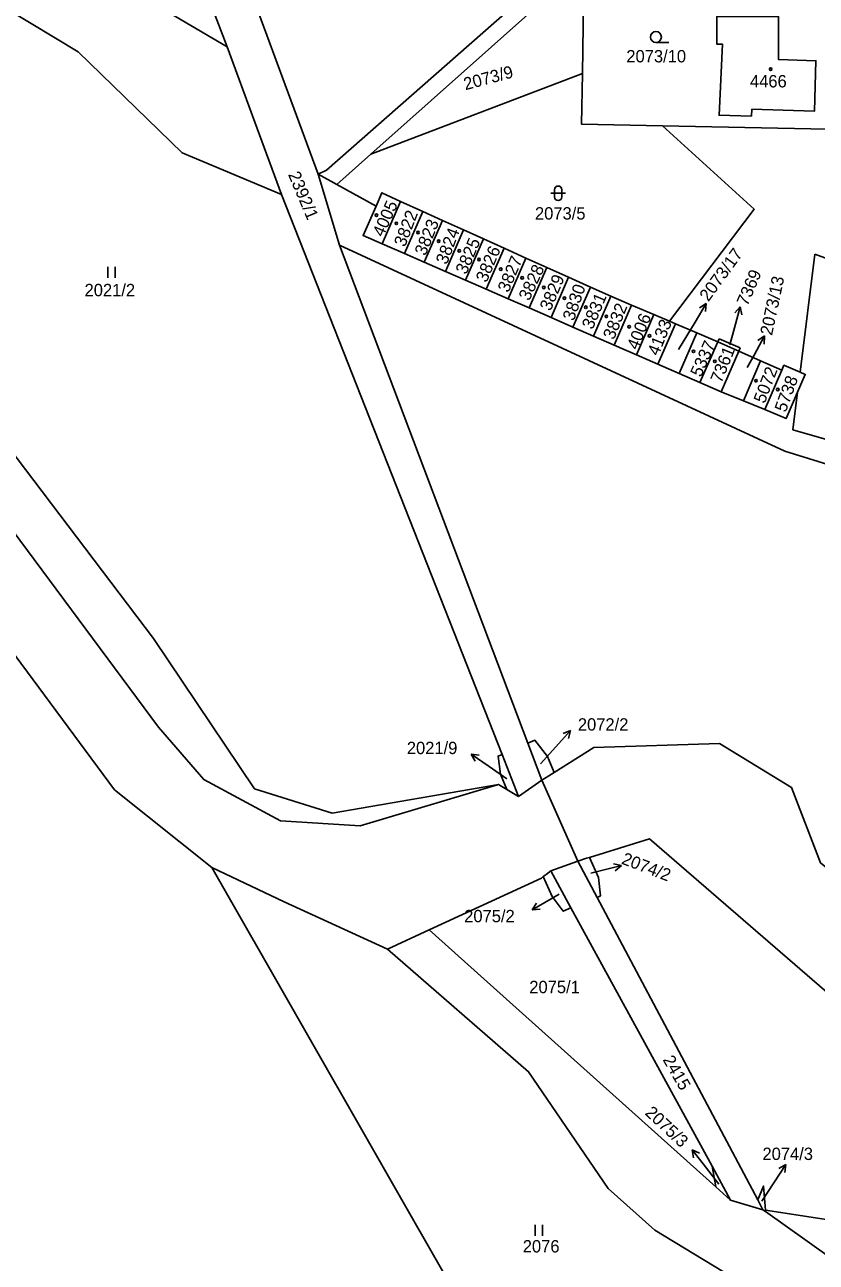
# Model space of a CAD drawing. Extents: x -667048 to -665920, y -1108425 to -1107247.
# Drawn here: x -666229.9 to -666121, y -1108187.1 to -1108016.8 of the extents above; entities that cross this region are included whole.
import ezdxf

# ---------------------------------------------------------------- set-up
doc = ezdxf.new("R2010")
doc.units = 0
for name, color, linetype in [('Default', 7, 'Continuous'), ('Hranice parcel', 7, 'Continuous'), ('Parcelní čísla', 7, 'Continuous'), ('Pop_ PČ_ popisy', 7, 'Continuous'), ('Značky budov', 7, 'Continuous'), ('Značky kultur', 7, 'Continuous')]:
    doc.layers.add(name, color=color, linetype=linetype)

# ---------------------------------------------------------------- blocks, each defined once
blk = doc.blocks.new('3.041')
at = {"layer": 'Default'}
blk.add_line((8, 0), (1758, 0), dxfattribs=at)
blk.add_circle((8, 750), 750, dxfattribs=at)
blk = doc.blocks.new('4.021')
at = {"layer": 'Default'}
blk.add_circle((-7, 1), 175, dxfattribs=at)
blk = doc.blocks.new('3.161')
at = {"layer": 'Default'}
for p, q in [((-1000, 1000), (1000, 1000)), ((-500, 1500), (-500, 500)), ((500, 500), (500, 1500))]:
    blk.add_line(p, q, dxfattribs=at)
for centre, start, end in [((0, 1500), 0, 180), ((0, 500), 180, 359.98789)]:
    blk.add_arc(centre, 500, start, end, dxfattribs=at)
blk = doc.blocks.new('10291')
at = {"layer": 'Default'}
for p, q in [((0, 3001), (-500, 2001)), ((0, 1), (0, 3001)), ((0, 3001), (500, 2001))]:
    blk.add_line(p, q, dxfattribs=at)
blk = doc.blocks.new('3.061')
at = {"layer": 'Default'}
for p, q in [((-511, -1), (-511, 1499)), ((489, -1), (489, 1499))]:
    blk.add_line(p, q, dxfattribs=at)

msp = doc.modelspace()

# ---------------------------------------------------------------- linework, layer by layer
at = {"layer": 'Hranice parcel'}
for points in [[(-666367.6, -1107733.37), (-666382.25, -1107746.6), (-666386.05, -1107757.21), (-666386.95, -1107822.21), (-666377, -1107854.78), (-666312.82, -1107976.82), (-666211.46, -1108113.47), (-666205.22, -1108120.66), (-666194.69, -1108126.35), (-666183.7, -1108127.05), (-666164.66, -1108121.36)], [(-666194.54, -1108040.18), (-666208.21, -1108034.43), (-666222.53, -1108020.57), (-666296.79, -1107975.73), (-666311.08, -1107963.6), (-666312.87, -1107961.82)], [(-666214.88, -1107968.55), (-666193.61, -1107981.03), (-666157.63, -1107981.49), (-666157.93, -1108008.07), (-666158.55, -1108010.61), (-666188.36, -1108036.81), (-666189.5, -1108037.4)], [(-666214.88, -1107968.55), (-666189.5, -1108037.4)], [(-666308.12, -1107969.91), (-666292.75, -1107996.41), (-666271.46, -1108022.33), (-666235.68, -1108070.26), (-666212.14, -1108101.26), (-666198.27, -1108121.92), (-666187.57, -1108125.3), (-666164.66, -1108121.36)], [(-666320.26, -1107983.17), (-666217.49, -1108122.07), (-666204.14, -1108132.75)], [(-666202.03, -1108019.86), (-666212.57, -1107992.25)], [(-666182.24, -1108034.63), (-666157.34, -1108012.43), (-666154.99, -1108010.84), (-666152.92, -1108010.37)], [(-666153.12, -1108023.51), (-666152.92, -1108010.37)], [(-666202.03, -1108019.86), (-666214.13, -1108012.7)], [(-666129.85, -1108029.41), (-666134.32, -1108029.28), (-666133.84, -1108019.5), (-666134.65, -1108019.49), (-666134.65, -1108015.69), (-666126.14, -1108015.7), (-666126.15, -1108021.62), (-666121, -1108021.77), (-666121.2, -1108028.69), (-666129.82, -1108028.44), (-666129.85, -1108029.41)], [(-666198.22, -1108030.21), (-666202.03, -1108019.86)], [(-666117.06, -1108022.14), (-666117.18, -1108031.25), (-666142.12, -1108030.72)], [(-666153.12, -1108023.51), (-666182.24, -1108034.63)], [(-666142.12, -1108030.72), (-666153.26, -1108030.49), (-666153.12, -1108023.51)], [(-666194.54, -1108040.18), (-666198.22, -1108030.21)], [(-666141.14, -1108057.61), (-666129.51, -1108042.2), (-666142.12, -1108030.72)], [(-666186.91, -1108038.79), (-666182.24, -1108034.63)], [(-666189.5, -1108037.4), (-666186.54, -1108047.13)], [(-666189.5, -1108037.4), (-666186.91, -1108038.79)], [(-666186.91, -1108038.79), (-666181.53, -1108041.76)], [(-666164.19, -1108117.23), (-666194.54, -1108040.18)], [(-666181.53, -1108041.76), (-666180.73, -1108039.94), (-666178.14, -1108041.12)], [(-666178.14, -1108041.12), (-666180.68, -1108046.96)], [(-666178.14, -1108041.12), (-666175.08, -1108042.51)], [(-666180.68, -1108046.96), (-666183.3, -1108045.82), (-666181.53, -1108041.76)], [(-666177.6, -1108048.3), (-666175.08, -1108042.51)], [(-666175.08, -1108042.51), (-666172.39, -1108043.73)], [(-666174.89, -1108049.48), (-666172.39, -1108043.73)], [(-666172.39, -1108043.73), (-666169.49, -1108045.04)], [(-666171.97, -1108050.75), (-666169.49, -1108045.04)], [(-666169.49, -1108045.04), (-666166.75, -1108046.28)], [(-666169.22, -1108051.95), (-666166.75, -1108046.28)], [(-666166.75, -1108046.28), (-666163.91, -1108047.56)], [(-666160.63, -1108115.67), (-666186.54, -1108047.13)], [(-666186.54, -1108047.13), (-666125.26, -1108075.48), (-666112.86, -1108079.33), (-666065.13, -1108092.87), (-666009.99, -1108116.41), (-665977.71, -1108122.7), (-665927.32, -1108129.44)], [(-666177.6, -1108048.3), (-666180.68, -1108046.96)], [(-666166.36, -1108053.2), (-666163.91, -1108047.56)], [(-666163.91, -1108047.56), (-666160.9, -1108048.92)], [(-666174.89, -1108049.48), (-666177.6, -1108048.3)], [(-666171.97, -1108050.75), (-666174.89, -1108049.48)], [(-666163.34, -1108054.52), (-666160.9, -1108048.92)], [(-666160.9, -1108048.92), (-666158.04, -1108050.21)], [(-666121.17, -1108048.37), (-666123.18, -1108064.62)], [(-666011.71, -1108072.54), (-666017.56, -1108086.38), (-666121.17, -1108048.37)], [(-666169.22, -1108051.95), (-666171.97, -1108050.75)], [(-666160.46, -1108055.78), (-666158.04, -1108050.21)], [(-666158.04, -1108050.21), (-666155.04, -1108051.57)], [(-666166.36, -1108053.2), (-666169.22, -1108051.95)], [(-666163.34, -1108054.52), (-666166.36, -1108053.2)], [(-666157.45, -1108057.1), (-666155.04, -1108051.57)], [(-666155.04, -1108051.57), (-666152.04, -1108052.93)], [(-666154.43, -1108058.42), (-666152.04, -1108052.93)], [(-666152.04, -1108052.93), (-666149.22, -1108054.17)], [(-666160.46, -1108055.78), (-666163.34, -1108054.52)], [(-666151.61, -1108059.66), (-666149.22, -1108054.17)], [(-666149.22, -1108054.17), (-666146.37, -1108055.38)], [(-666157.45, -1108057.1), (-666160.46, -1108055.78)], [(-666148.77, -1108060.89), (-666146.37, -1108055.38)], [(-666146.37, -1108055.38), (-666143.29, -1108056.69)], [(-666154.43, -1108058.42), (-666157.45, -1108057.1)], [(-666145.7, -1108062.22), (-666143.29, -1108056.69)], [(-666143.29, -1108056.69), (-666141.14, -1108057.61)], [(-666140.34, -1108057.95), (-666142.76, -1108063.5)], [(-666141.14, -1108057.61), (-666140.34, -1108057.95)], [(-666140.34, -1108057.95), (-666137.38, -1108059.21)], [(-666151.61, -1108059.66), (-666154.43, -1108058.42)], [(-666148.77, -1108060.89), (-666151.61, -1108059.66)], [(-666139.81, -1108064.78), (-666137.38, -1108059.21)], [(-666137.38, -1108059.21), (-666134.52, -1108060.43)], [(-666134.52, -1108060.43), (-666134.34, -1108060.01)], [(-666134.34, -1108060.01), (-666131.41, -1108061.29)], [(-666145.7, -1108062.22), (-666148.77, -1108060.89)], [(-666136.96, -1108066.02), (-666134.52, -1108060.43)], [(-666131.59, -1108061.71), (-666134.52, -1108060.43)], [(-666131.59, -1108061.71), (-666134.02, -1108067.3)], [(-666131.41, -1108061.29), (-666131.59, -1108061.71)], [(-666131.59, -1108061.71), (-666128.61, -1108063.05)], [(-666142.76, -1108063.5), (-666145.7, -1108062.22)], [(-666130.99, -1108068.54), (-666128.61, -1108063.05)], [(-666128.61, -1108063.05), (-666125.71, -1108064.36)], [(-666142.76, -1108063.5), (-666139.81, -1108064.78)], [(-666136.96, -1108066.02), (-666139.81, -1108064.78)], [(-666128.04, -1108069.74), (-666125.71, -1108064.36)], [(-666125.71, -1108064.36), (-666125.41, -1108063.66), (-666123.18, -1108064.62)], [(-666123.18, -1108064.62), (-666122.47, -1108064.93), (-666123.52, -1108067.36)], [(-666134.02, -1108067.3), (-666136.96, -1108066.02)], [(-666134.02, -1108067.3), (-666130.99, -1108068.54)], [(-666123.52, -1108067.36), (-666125.11, -1108071.01), (-666128.04, -1108069.74)], [(-666123.52, -1108067.36), (-666124.17, -1108072.57)], [(-666128.04, -1108069.74), (-666130.99, -1108068.54)], [(-666124.17, -1108072.57), (-666064.15, -1108089.77), (-666009.29, -1108113.1), (-665977.25, -1108119.58), (-665927.32, -1108126.18)], [(-666160.63, -1108115.67), (-666159.66, -1108115.25), (-666157.93, -1108117.51), (-666157.01, -1108119.68)], [(-666158.71, -1108120.75), (-666160.63, -1108115.67)], [(-666157.01, -1108119.68), (-666151.55, -1108116.25), (-666134.26, -1108115.7), (-666124.35, -1108121.77), (-666120.37, -1108132.13), (-666109.74, -1108140.9), (-666074.44, -1108140.6), (-666051.14, -1108146.66), (-666030.68, -1108162.7), (-665999.31, -1108182.94), (-665978.14, -1108198.63), (-665960.5, -1108216.92), (-665949.27, -1108234.66), (-665927.32, -1108251.64)], [(-666163.53, -1108122.03), (-666164.4, -1108119.93), (-666164.74, -1108117.44), (-666164.19, -1108117.23)], [(-666164.19, -1108117.23), (-666161.92, -1108122.98)], [(-666161.92, -1108122.98), (-666158.71, -1108120.75)], [(-666158.71, -1108120.75), (-666157.4, -1108119.92), (-666157.01, -1108119.68)], [(-666153.76, -1108131.87), (-666158.71, -1108120.75)], [(-666164.66, -1108121.36), (-666163.53, -1108122.03)], [(-666161.92, -1108122.98), (-666162.86, -1108122.43), (-666163.53, -1108122.03)], [(-665957.88, -1108245.03), (-665984.95, -1108209.07), (-666010.44, -1108185.66), (-666037.45, -1108174.12), (-666061.27, -1108156.51), (-666115.42, -1108153.44), (-666143.9, -1108128.81), (-666152.14, -1108131.37)], [(-666152.14, -1108131.37), (-666152.55, -1108131.49), (-666153.76, -1108131.87)], [(-666151.1, -1108136.87), (-666150.66, -1108136.68), (-666150.94, -1108134.12), (-666152.14, -1108131.37)], [(-666179.96, -1108144.01), (-666194.17, -1108137.48), (-666204.14, -1108132.75)], [(-666204.14, -1108132.75), (-666135.41, -1108252.89)], [(-666157.48, -1108133.24), (-666153.76, -1108131.87)], [(-666151.1, -1108136.87), (-666153.76, -1108131.87)], [(-666174.2, -1108141.34), (-666158.77, -1108134.21), (-666158.51, -1108134.01)], [(-666158.51, -1108134.01), (-666158.13, -1108133.73), (-666157.48, -1108133.24)], [(-666154.71, -1108138.3), (-666155.77, -1108138.78), (-666157.31, -1108136.75), (-666158.51, -1108134.01)], [(-666157.48, -1108133.24), (-666154.71, -1108138.3)], [(-666154.71, -1108138.3), (-666135.3, -1108173.84)], [(-666151.1, -1108136.87), (-666129.02, -1108178.47)], [(-666179.96, -1108144.01), (-666174.2, -1108141.34)], [(-666134.76, -1108176.71), (-666174.2, -1108141.34)], [(-666133.7, -1108188.39), (-666143.18, -1108182.64), (-666149.6, -1108176.9), (-666160.53, -1108160.87), (-666179.96, -1108144.01)], [(-666135.3, -1108173.84), (-666132.75, -1108178.51)], [(-666134.76, -1108176.71), (-666135.3, -1108173.84)], [(-666132.75, -1108178.51), (-666134.76, -1108176.71)], [(-666129.02, -1108178.47), (-666128.21, -1108176.6), (-666127.94, -1108179.89)], [(-666128.29, -1108179.84), (-666132.75, -1108178.51)], [(-666128.29, -1108179.84), (-666129.02, -1108178.47)], [(-666127.93, -1108180.1), (-666128.29, -1108179.84)], [(-666127.94, -1108179.89), (-666127.93, -1108180.1)], [(-666127.94, -1108179.89), (-666084.69, -1108186.57), (-666061.76, -1108189.5), (-666037.52, -1108196.85), (-665981.57, -1108223.66), (-665957.88, -1108245.03)], [(-665927.32, -1108275.69), (-665963.06, -1108243.86), (-666040.05, -1108204.21), (-666063.13, -1108194.59), (-666078.83, -1108193.85), (-666081.36, -1108193.73), (-666110.76, -1108192.34), (-666127.93, -1108180.1)]]:
    msp.add_lwpolyline(points, dxfattribs=at)
at = {"layer": 'Pop_ PČ_ popisy'}
for points in [[(-666139.92, -1108061.52), (-666137.64, -1108057.72)], [(-666132.85, -1108060.86), (-666132.21, -1108058.51)], [(-666130.48, -1108063.97), (-666129.52, -1108062.26)], [(-666158.9, -1108118.5), (-666156.77, -1108116.15)], [(-666163.51, -1108120.57), (-666165.97, -1108118.87)], [(-666151.96, -1108133.53), (-666150.67, -1108133.21)], [(-666156.33, -1108136.42), (-666157.45, -1108137.08)], [(-666134.37, -1108176.31), (-666136.2, -1108173.96)], [(-666128.43, -1108178.65), (-666126.79, -1108176.14)]]:
    msp.add_lwpolyline(points, dxfattribs=at)

# ---------------------------------------------------------------- block references
for p, xscale, yscale, rotation in [((-666137.64, -1108057.72), 0.001, 0.001, -31.000000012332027), ((-666132.21, -1108058.51), 0.0010000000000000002, 0.0010000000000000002, -14.999999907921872), ((-666129.52, -1108062.26), 0.001, 0.0010000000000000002, -29.000000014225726), ((-666156.77, -1108116.15), 0.001, 0.0010000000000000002, -41.99999994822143), ((-666165.97, -1108118.87), 0.001, 0.0010000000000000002, 54.99999996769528), ((-666150.67, -1108133.21), 0.0010000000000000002, 0.001, -75.99999997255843), ((-666157.45, -1108137.08), 0.001, 0.0010000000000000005, 119.99999996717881), ((-666136.2, -1108173.96), 0.0010000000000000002, 0.0010000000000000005, 38.00000002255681), ((-666126.79, -1108176.14), 0.001, 0.0010000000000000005, -32.99999998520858)]:
    msp.add_blockref('10291', p, dxfattribs=dict(at, xscale=xscale, yscale=yscale, rotation=rotation))
at = {"layer": 'Značky budov', "xscale": 0.0010000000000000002, "yscale": 0.0010000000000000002}
for p in [(-666127.23, -1108022.93), (-666181.47, -1108043.02), (-666178.73, -1108044.14), (-666175.74, -1108045.4), (-666172.91, -1108046.6), (-666170.07, -1108047.92), (-666167.35, -1108049.12), (-666164.36, -1108050.44), (-666161.42, -1108051.64), (-666158.43, -1108052.96), (-666155.6, -1108054.43), (-666152.66, -1108055.69), (-666149.83, -1108056.95), (-666146.7, -1108058.37), (-666143.9, -1108059.62), (-666137.84, -1108061.75), (-666134.9, -1108063.12), (-666129.24, -1108065.8), (-666126.25, -1108067)]:
    msp.add_blockref('4.021', p, dxfattribs=at)
at = {"layer": 'Značky kultur', "xscale": 0.0010000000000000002, "yscale": 0.0010000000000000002}
for name, p in [('3.041', (-666143.02, -1108019.26)), ('3.161', (-666156.46, -1108041.01)), ('3.061', (-666217.9, -1108051.62)), ('3.061', (-666159.13, -1108183.42))]:
    msp.add_blockref(name, p, dxfattribs=at)

# ---------------------------------------------------------------- texts
at = {"layer": 'Parcelní čísla'}
for s, p in [('2073/10', (-666147.09, -1108022)), ('4466', (-666130.08, -1108025.44)), ('2073/5', (-666159.66, -1108043.62)), ('2021/2', (-666221.63, -1108054.17)), ('2072/2', (-666153.76, -1108113.93)), ('2021/9', (-666177.29, -1108117.16)), ('2075/2', (-666169.4, -1108140.29)), ('2075/1', (-666160.44, -1108150.05)), ('2074/3', (-666128.36, -1108173)), ('2076', (-666161.34, -1108185.72))]:
    msp.add_text(s, height=1.7, dxfattribs=at).set_placement(p)
for s, rotation, p in [('2073/9', 15, (-666169.23, -1108025.84)), ('2392/1', 293, (-666193.66, -1108037.42)), ('4005', 66, (-666180.54, -1108046.12)), ('3822', 69, (-666177.54, -1108047.48)), ('3823', 68, (-666174.72, -1108048.7)), ('3824', 69, (-666171.79, -1108049.91)), ('3825', 67, (-666169.11, -1108051.27)), ('3826', 67, (-666166.32, -1108052.38)), ('2073/17', 54, (-666135.8, -1108055.01)), ('3827', 67, (-666163.31, -1108053.76)), ('3828', 65, (-666160.45, -1108054.9)), ('3829', 67, (-666157.52, -1108056.3)), ('7369', 67, (-666130.42, -1108055.62)), ('2073/13', 78, (-666127.05, -1108059.65)), ('3830', 71, (-666154.31, -1108057.66)), ('3831', 67, (-666151.73, -1108058.84)), ('3832', 68, (-666148.8, -1108060.25)), ('4006', 68, (-666145.52, -1108061.66)), ('4133', 68, (-666142.68, -1108062.47)), ('5337', 66, (-666136.82, -1108065.4)), ('7361', 68, (-666134.01, -1108066.22)), ('5072', 69, (-666128.06, -1108069.02)), ('5738', 70, (-666125.16, -1108070.24)), ('2074/2', 339, (-666147.87, -1108132.21)), ('2415', 300, (-666142.13, -1108159.2)), ('2075/3', 317, (-666144.64, -1108166.65))]:
    msp.add_text(s, height=1.7, rotation=rotation, dxfattribs=at).set_placement(p)

doc.saveas('drawing.dxf')
